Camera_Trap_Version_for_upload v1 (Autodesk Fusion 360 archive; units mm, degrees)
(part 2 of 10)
sketch "Sketch1" plane through (56.25, 0, 0) normal (1, 0, 0) x axis (0, 1, 0)
  line L1 (60.1013, 133) -> (0.1013, 133)
  line L2 (-49.8987, 133) -> (0.1013, 133)
  line L3 (-0.2, 163) -> (14.1326, 163)
  line L4 (16.8, 163) -> (16.8, 163.0335)
  line L5 (-3.2, 103) -> (16.8, 163)
  line L6 (16.8, 103) -> (-3.2, 163)
  line L7 (60, 152.0335) -> (27.8, 152.0335)
  line L8 (60.1013, 133) -> (60, 152.0335)
  line L9 (60.1013, 133) -> (16.8, 133)
  line L10 (60, 100) -> (60, 165)
  line L11 (-3.2, 133) -> (-3.2, 160)
  line L12 (-3.2, 117.4356) -> (-3.2, 119.4382)
  line L13 (-3.2, 133) -> (60.1013, 133)
  line L14 (60.1013, 133) -> (60, 113.9665)
  line L15 (60, 113.9665) -> (27.8, 113.9665)
  line L16 (-0.2, 103) -> (14.1326, 103)
  line L17 (-3.2, 133) -> (-3.2, 106)
  line L18 (6.9663, 163) -> (6.8, 133)
  line L19 (6.9663, 103) -> (6.8, 133)
  line L20 (20, 157) -> (-5, 157)
  line L21 (20, 155.6) -> (20, 157)
  line L22 (-5, 155.6) -> (20, 155.6)
  line L23 (-5, 157) -> (-5, 155.6)
  line L24 (20, 109) -> (-5, 109)
  line L25 (-5, 109) -> (-5, 110.4)
  line L26 (-5, 110.4) -> (20, 110.4)
  line L27 (20, 110.4) -> (20, 109)
  circle C1 centre (6.8, 133) radius 18.4
  circle C2 centre (6.8, 133) radius 16.85
  circle C3 centre (6.8, 133) radius 18.5
  arc A1 centre (27.8, 163.0335) radius 11 clockwise from (27.8, 152.0335) to (17.0613, 160.65)
  arc A2 centre (14.1326, 160) radius 3 clockwise from (14.1326, 163) to (17.0613, 160.65)
  arc A3 centre (-0.2, 160) radius 3 clockwise from (-3.2, 160) to (-0.2, 163)
  arc A4 centre (27.8, 102.9665) radius 11 clockwise from (17.0613, 105.35) to (27.8, 113.9665)
  arc A5 centre (14.1326, 106) radius 3 clockwise from (17.0613, 105.35) to (14.1326, 103)
  arc A6 centre (-0.2, 106) radius 3 clockwise from (-0.2, 103) to (-3.2, 106)
  point P4 (6.8, 133)
  point P12 (6.8, 133)
  point P2 (6.8, 133)
  point P14 (16.8, 133)
  point P11 (16.8, 103)
  point P9 (-3.2, 163)
  point P26 (-3.2, 133)
  point P27 (-3.2, 119.4382)
  point P28 (-3.2, 117.4356)
  point P6 (60.1013, 133)
  point P30 (60.1013, 133)
  point P13 (60, 152.0335)
  point P29 (60, 113.9665)
  point P16 (27.8, 152.0335)
  point P31 (27.8, 113.9665)
  point P18 (14.1326, 163)
  point P35 (14.1326, 103)
  point P19 (17.0613, 160.65)
  point P33 (17.0613, 105.35)
  point P21 (-3.2, 160)
  point P38 (-3.2, 106)
  point P22 (-0.2, 163)
  point P36 (-0.2, 103)
  point P39 (-3.2, 133)
  point P40 (6.8, 133)
  point P41 (6.9663, 163)
  point P42 (6.8, 133)
  point P43 (6.9663, 103)
  point P44 (-5, 157)
  point P48 (-5, 109)
  point P45 (20, 157)
  point P49 (20, 109)
  point P46 (20, 155.6)
  point P51 (20, 110.4)
  point P47 (-5, 155.6)
  point P50 (-5, 110.4)
  point P5 (0.1013, 133)
  point P7 (-49.8987, 133)
  point P10 (-3.2, 103)
  concentric C1 C2
  concentric C1 C3
  horizontal L1
  parallel L1 L2
  coincident P4 L1
  horizontal L3
  perpendicular L3 L11
  parallel L4 L11
  coincident L5 P12
  coincident L6 P12
  coincident P2 P12
  perpendicular L4 L7
  coincident L4 P14
  coincident P11 L4
  tangent L4 A1
  tangent L7 A1
  tangent L3 A2
  tangent A1 A2
  coincident P9 L11
  coincident P9 L3
  tangent A3 L11
  tangent L3 A3
  equal A2 A3
  vertical L10
  coincident L2 P26
  coincident C2 P27
  collinear L11 L12
  coincident C3 P28
  symmetric P6 L2 P30
  symmetric L2 P13 P29
  symmetric L2 P16 P31
  symmetric L2 A1 A4
  symmetric L2 P18 P35
  symmetric L2 P19 P33
  symmetric L2 A2 A5
  symmetric L2 P21 P38
  symmetric L2 P22 P36
  symmetric L2 A3 A6
  symmetric L2 P26 P39
  coincident P4 P40
  midpoint L3 P41
  coincident P4 P42
  midpoint L16 P43
  horizontal L20
  vertical L21
  horizontal L22
  vertical L23
  symmetric L2 P44 P48
  symmetric L2 P45 P49
  symmetric L2 P46 P51
  symmetric L2 P47 P50
  dimension "d254" diameter C2 = 33.7
  dimension "d255" diameter C3 = 37
  dimension "d256" distance P5 P6 = 60
  dimension "d257" distance P5 P7 = 50
  dimension "d258" distance P10 P11 = 20
  dimension "d259" distance P9 P10 = 60
  dimension "d260" radius A1 = 11
  dimension "d261" radius A2 = 3
  dimension "d266" distance P44 P45 = 25
  dimension "d267" distance P44 P47 = 1.4
extrude "Extrude1" new body sketch "Sketch1" profile of C1 C2 C3 L3 L7 L9 A1 A2 L10 L13 L15 A4 A5 L16 L18 L19 L20 L22 L24 L26 distance 5 bodies "interior_motor_holder"
extrude "Extrude2" new body sketch "Sketch1" profile of C1 C2 C3 L3 L12 A3 L16 A6 L17 L18 L19 L20 L22 L24 L26 distance 5 bodies "exterior_motor_holder"
revolve "Revolve1" sketch "Sketch1" AlongAngle 360 bodies "upper_pin"
revolve "Revolve2" sketch "Sketch1" AlongAngle 360 bodies "lower_pin"
combine "Combine1"
combine "Combine2"
combine "Combine3"
combine "Combine4"
sketch "LL_pin" plane through (0, 0, 0) normal (0, 1, 0) x axis (1, 0, 0)
  line L1 (200, 0) -> (-200, 0)
  line L2 (0, -70) -> (0, 0)
  line L3 (-11, -70) -> (5, -70)
  line L4 (-11, -74.1) -> (-11, -70)
  line L5 (5, -70) -> (5, -74.1)
  line L6 (-5, -70) -> (-3, -70)
  line L7 (-5, -75) -> (-5, -74.1)
  line L8 (-3, -75) -> (-5, -75)
  line L9 (-3, -74.1) -> (-3, -75)
  line L10 (-5, -74.1) -> (-11, -74.1)
  line L11 (5, -74.1) -> (-3, -74.1)
  point P1 (0, 0)
  point P4 (0, 0)
  point P10 (-3, -70)
  point P2 (-200, 0)
  point P3 (200, 0)
  point P5 (0, -70)
  point P6 (5, -70)
  point P7 (-11, -70)
  point P9 (5, -74.1)
  point P11 (-5, -70)
  point P13 (-3, -75)
  horizontal L1
  coincident P1 P4
  perpendicular L1 L2
  horizontal L3
  vertical L4
  horizontal L10
  vertical L5
  horizontal L6
  vertical L7
  horizontal L8
  vertical L9
  midpoint L3 P10
  collinear L10 L11
  dimension "d120_3_1" distance P2 P3 = 400
  dimension "d122_3_1" distance P4 P5 = 70
  dimension "d123_3_1" distance P6 P7 = 16 (= "LL_Pin_Length")
  dimension "d124_3_1" distance P6 P9 = 4.1 (= "LL_Pin_half_height")
  dimension "d129_3_1" distance P10 P11 = 2 (= "LL_lip_length")
  dimension "d130_3_1" distance P10 P13 = 5 (= "LL_lip_half_height")
revolve "Revolve1" sketch "LL_pin" AlongAngle 360 named "d131_3_1" bodies "S2_L_Pin"
sketch "LL_pin_falt_face" plane through (5, 0, 0) normal (1, 0, 0) x axis (0, 1, 0)
  line L1 (0, 67) -> (0, 70)
  line L2 (2.8039, 67.0087) -> (-2.8039, 67.0087)
  circle C1 centre (0, 70) radius 4.1
  point P2 (0, 70)
  point P3 (0, 70)
  point P5 (-2.8039, 67.0087)
  point P6 (2.8039, 67.0087)
  coincident P2 P3
  vertical L1
  coincident C1 P5
  coincident C1 P6
  perpendicular L1 L2
extrude "Extrude1" cut sketch "LL_pin_falt_face" profile of C1 L2 against normal blind 5 named "d132_3_1"
fillet "Fillet1" radius 1 named "d135_3_1"
position "Position5"
sketch "Sketch1" plane through (-11, 0, 0) normal (-1, 0, 0) x axis (0, -1, 0)
  circle C1 centre (0, 70) radius 4.1
  circle C2 centre (0, 70) radius 11
  concentric C1 C2
  dimension "d180_1" diameter C2 = 22
extrude "Extrude1" new body sketch "Sketch1" along normal blind 1 named "d181_1" and against normal blind 6 named "d183_1" bodies "L_ball_bearing"
position "Position6"
remove_instance "RemoveInstance12"
position "Position4"
extrude "Extrude14" new body sketch "Tests" profile of C7 C8 along normal blind 3 bodies "348"
extrude "Extrude15" new body sketch "Tests" profile of C9 C10 along normal blind 3 bodies "340"
extrude "Extrude16" new body sketch "Tests" profile of C11 C12 along normal blind 3 bodies "342"
extrude "Extrude17" new body sketch "Tests" profile of C13 C14 along normal blind 3 bodies "344"
extrude "Extrude18" new body sketch "Tests" profile of C13 C14 along normal blind 24 bodies "343"
extrude "Extrude6" cut sketch "Sketch1" profile of C1 C3 L7 along normal blind 1.2
copy_paste "CopyPaste1"
revolve "Revolve1" sketch "Sketch2" AlongAngle 360
revolve "Revolve3" sketch "Sketch2" AlongAngle 360
combine "Combine1" bodies "Mid_gear"
remove_instance "RemoveInstance13"
sketch "Sketch1" plane through (-11, 0, 0) normal (-1, 0, 0) x axis (0, -1, 0)
  circle C1 centre (0, 70) radius 4.1
  circle C2 centre (0, 70) radius 11
  concentric C1 C2
  dimension "d180_2" diameter C2 = 22
extrude "Extrude1" new body sketch "Sketch1" along normal blind 1 named "d181_2" and against normal blind 6 named "d183_2" bodies "L_ball_bearing"
sketch "Sketch1" plane through (0, 0, 0) normal (0, 0, 1) x axis (1, 0, 0)
  curve K1 (31.9963, -0.4887) -> (29.9991, -0.9267)
  curve K2 (31.9963, 0.4887) -> (29.9991, 0.9267)
  curve K3 (29.9991, -0.9267) -> (29.9983, -0.9266)
  curve K4 (29.9991, 0.9267) -> (29.9983, 0.9266)
  line L1 (29.9983, -0.9266) -> (0, 0)
  line L2 (29.9983, 0.9266) -> (0, 0)
  line L3 (0, 0) -> (0, 0)
  line L4 (0, 0) -> (0, 0)
  arc A1 centre (0, 0) radius 32 clockwise from (31.9963, 0.4887) to (31.9963, -0.4887)
sketch "Sketch2" plane through (0, 0, 0) normal (0, 0, 1) x axis (1, 0, 0)
  circle C1 centre (0, 0) radius 29.75
extrude "Extrude1" new body sketch "Sketch2" along normal blind 3 named "d88_1"
sweep "Sweep1" sketch "Sketch1" TwistAngle 1.5 named "d94_1" TaperAngle 0 named "d95_1"
circular_pattern "C-Pattern1" countU 62 named "d96_1" TotalAngle 360 named "d97_1"
combine "Combine1"
work_plane "WorkPlane1" AlongDistance 3 named "d98_1"
mirror "Mirror1" mirrorStitchTolerance 0.01 named "d100_1"
combine "Combine2"
sketch "Sketch3" plane through (0, 0, 0) normal (0, 0, 1) x axis (1, 0, 0)
  curve K1 (87.334, 0) -> (0, 0)
  curve K2 (87.334, 3) -> (87.334, 0)
  curve K3 (0, 3) -> (87.334, 3)
  curve K4 (0, 0) -> (0, 3)
  perpendicular K1 K2
  parallel K1 K3
  parallel K2 K4
position "Position7"
copy_paste "CutPaste4"
combine "Combine5"
combine "Combine1" bodies "Mid_gear"
fillet "Fillet1" radius 3.5
sketch "LL_pin" plane through (0, 0, 0) normal (0, 1, 0) x axis (1, 0, 0)
  line L1 (200, 0) -> (-200, 0)
  line L2 (0, -70) -> (0, 0)
  line L3 (-11, -70) -> (5, -70)
  line L4 (-11, -74.1) -> (-11, -70)
  line L5 (5, -70) -> (5, -74.1)
  line L6 (-5, -70) -> (-3, -70)
  line L7 (-5, -75) -> (-5, -74.1)
  line L8 (-3, -75) -> (-5, -75)
  line L9 (-3, -74.1) -> (-3, -75)
  line L10 (-5, -74.1) -> (-11, -74.1)
  line L11 (5, -74.1) -> (-3, -74.1)
  point P1 (0, 0)
  point P4 (0, 0)
  point P10 (-3, -70)
  point P2 (-200, 0)
  point P3 (200, 0)
  point P5 (0, -70)
  point P6 (5, -70)
  point P7 (-11, -70)
  point P9 (5, -74.1)
  point P11 (-5, -70)
  point P13 (-3, -75)
  horizontal L1
  coincident P1 P4
  perpendicular L1 L2
  horizontal L3
  vertical L4
  horizontal L10
  vertical L5
  horizontal L6
  vertical L7
  horizontal L8
  vertical L9
  midpoint L3 P10
  collinear L10 L11
  dimension "d120_3" distance P2 P3 = 400
  dimension "d122_3" distance P4 P5 = 70
  dimension "d123_3" distance P6 P7 = 16 (= "LL_Pin_Length")
  dimension "d124_3" distance P6 P9 = 4.1 (= "LL_Pin_half_height")
  dimension "d129_3" distance P10 P11 = 2 (= "LL_lip_length")
  dimension "d130_3" distance P10 P13 = 5 (= "LL_lip_half_height")
revolve "Revolve1" sketch "LL_pin" AlongAngle 360 named "d131_3" bodies "S3_L_Pin"
sketch "LL_pin_falt_face" plane through (5, 0, 0) normal (1, 0, 0) x axis (0, 1, 0)
  line L1 (0, 67) -> (0, 70)
  line L2 (2.8039, 67.0087) -> (-2.8039, 67.0087)
  circle C1 centre (0, 70) radius 4.1
  point P2 (0, 70)
  point P3 (0, 70)
  point P5 (-2.8039, 67.0087)
  point P6 (2.8039, 67.0087)
  coincident P2 P3
  vertical L1
  coincident C1 P5
  coincident C1 P6
  perpendicular L1 L2
extrude "Extrude1" cut sketch "LL_pin_falt_face" profile of C1 L2 against normal blind 8 named "d132_3"
position "Position8"
combine "Combine3"
work_plane "WorkPlane1" RotateAngle 0
sketch "Sketch1" plane through (3, 0, 0) normal (-1, 0, 0) x axis (0, 0, 1)
sketch "Sketch1" plane through (0, 0, 0) normal (0, 1, 0) x axis (1, 0, 0)
  line L1 (-5, -185) -> (-5, -207)
  line L2 (-12, -207) -> (-12, -185)
  line L3 (-12, -185) -> (-5, -185)
  line L4 (-12, -207) -> (-5, -207)
  line L5 (5, -193.0087) -> (-3, -193.0087)
  line L6 (5, -200.1) -> (5, -193.0087)
  line L7 (-5, -191.9) -> (-5, -191)
  line L8 (-5, -201) -> (-5, -200.1)
  line L9 (-11, -200.1) -> (-11, -191.9)
  line L10 (-3, -200.1) -> (5, -200.1)
  line L11 (-5, -191) -> (-3, -191)
  line L12 (-5, -201) -> (-3, -201)
  line L13 (-11, -191.9) -> (-5, -191.9)
  line L14 (-11, -200.1) -> (-5, -200.1)
  line L15 (-12.9524, -212.0635) -> (-8, -212.0635)
  line L16 (-15.9524, -182.8039) -> (-15.9524, -209.0635)
  line L17 (-5, -209.0635) -> (-5, -182.8039)
  line L18 (-12, -189.5) -> (-11, -189.5)
  line L19 (-12, -202.5) -> (-12, -189.5)
  line L20 (-11, -202.5) -> (-12, -202.5)
  line L21 (-11, -189.5) -> (-11, -202.5)
  line L22 (-12, -202.5) -> (-11, -189.5)
  line L23 (-11, -202.5) -> (-12, -189.5)
  line L24 (-21, -200.1) -> (-11, -200.1)
  line L25 (-21, -191.9) -> (-21, -200.1)
  line L26 (-11, -191.9) -> (-21, -191.9)
  line L27 (-11, -200.1) -> (-11, -191.9)
  line L28 (-14.134, -166.1795) -> (-5.4019, -181.3039)
  line L29 (15, -182) -> (-5, -182)
  line L30 (5, -182) -> (-15.9524, -182)
  line L31 (-21.7259, -175) -> (-24.9206, -175)
  line L32 (-24.9206, -164.6795) -> (-16.7321, -164.6795)
  line L33 (-25.9206, -175) -> (-25.9206, -164.6795)
  line L34 (-19.1278, -176.5) -> (-16.3543, -181.3039)
  line L35 (-25.9524, -164.6795) -> (-25.9206, -164.7346)
  line L36 (-25.9206, -189) -> (-25.9206, -176)
  line L37 (-25.9206, -159.1567) -> (-25.9206, -163.6795)
  line L38 (-25.9206, -189) -> (-25.9206, -159.1567)
  line L39 (-5, -185) -> (-5, -207)
  line L40 (-5, -207) -> (-12, -207)
  line L41 (-5, -185) -> (-5, -207)
  line L42 (-12, -185) -> (-5, -185)
  line L43 (-12, -207) -> (-12, -185)
  line L44 (-17.5, -200.1) -> (-16.5, -200.1)
  line L45 (-17.5, -191.9) -> (-17.5, -200.1)
  line L46 (-16.5, -191.9) -> (-17.5, -191.9)
  line L47 (-16.5, -200.1) -> (-16.5, -191.9)
  line L48 (-3, -193.0087) -> (-3, -191)
  line L49 (-3, -201) -> (-3, -200.1)
  arc A1 centre (-16.7321, -167.6795) radius 3 clockwise from (-16.7321, -164.6795) to (-14.134, -166.1795)
  arc A2 centre (-21.7259, -178) radius 3 clockwise from (-21.7259, -175) to (-19.1278, -176.5)
  arc A3 centre (-8, -182.8039) radius 3 clockwise from (-5.4019, -181.3039) to (-5, -182.8039)
  arc A4 centre (-8, -209.0635) radius 3 clockwise from (-5, -209.0635) to (-8, -212.0635)
  arc A5 centre (-12.9524, -209.0635) radius 3 clockwise from (-12.9524, -212.0635) to (-15.9524, -209.0635)
  arc A6 centre (-18.9524, -182.8039) radius 3 clockwise from (-16.3543, -181.3039) to (-15.9524, -182.8039)
  arc A7 centre (-24.9206, -176) radius 1 clockwise from (-25.9206, -176) to (-24.9206, -175)
  arc A8 centre (-24.9206, -163.6795) radius 1 clockwise from (-24.9206, -164.6795) to (-25.9206, -163.6795)
  point P26 (-11.5, -196)
  point P15 (-11, -200.1)
  point P27 (-11, -200.1)
  point P36 (-25.9206, -164.7346)
  point P21 (-5, -182)
  point P20 (-15.9524, -182)
  point P34 (-25.9206, -175)
  point P35 (-25.9206, -164.6795)
  point P2 (-5, -207)
  point P63 (-5, -207)
  point P3 (-5, -185)
  point P64 (-5, -185)
  point P5 (-12, -207)
  point P65 (-12, -207)
  point P68 (-16.5, -200.1)
  point P23 (-12, -189.5)
  point P24 (-12, -202.5)
  point P28 (-21, -200.1)
  point P32 (-25.9524, -164.6795)
  point P71 (-16.5, -191.9)
  horizontal L15
  vertical L16
  vertical L17
  horizontal L18
  perpendicular L18 L19
  parallel L18 L20
  parallel L19 L21
  coincident L22 P26
  coincident L23 P26
  horizontal L24
  vertical L25
  horizontal L26
  vertical L27
  coincident P15 P27
  horizontal L29
  horizontal L30
  horizontal L31
  horizontal L32
  vertical L33
  coincident L33 P36
  collinear L34 L35
  tangent L32 A1
  tangent L28 A1
  tangent L31 A2
  tangent L34 A2
  equal A1 A2
  coincident P21 L28
  coincident P21 L17
  tangent L28 A3
  tangent L17 A3
  equal A1 A3
  tangent L17 A4
  tangent L15 A4
  equal A1 A4
  tangent L15 A5
  tangent L16 A5
  equal A1 A5
  coincident P20 L34
  coincident P20 L16
  tangent L34 A6
  tangent L16 A6
  equal A1 A6
  perpendicular L31 L36
  coincident P34 L36
  coincident P34 L31
  tangent L36 A7
  tangent L31 A7
  vertical L37
  coincident P35 L32
  coincident P36 L37
  tangent L32 A8
  tangent L37 A8
  parallel L36 L38
  coincident P2 P63
  coincident P3 P64
  horizontal L40
  vertical L41
  horizontal L42
  vertical L43
  coincident P5 P65
  horizontal L44
  vertical L45
  horizontal L46
  vertical L47
  coincident L24 P68
  dimension "d276" distance P23 P24 = 13
  dimension "d277" distance P27 P28 = 10
  dimension "d278" angle L28 L29 = 120
  dimension "d280" angle L30 L34 = 120
  dimension "d281" distance P20 P32 = 20
  dimension "d282" radius A1 = 3
  dimension "d283" radius A7 = 1
  dimension "d284" radius A8 = 1
  dimension "d293" distance P68 P71 = 8.2
extrude "Extrude1" new body sketch "Sketch1" profile of L1 L2 L3 L4 L7 L8 L9 L13 L14 L15 L16 L17 L18 L19 L20 L21 L24 L26 L27 L28 L35 L31 L32 L33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 distance 13 bodies "Hanger"
fillet "Fillet1" radius 1.5
fillet "Fillet2" radius 1.5
extrude "Extrude2" add of existing geometry blind 10
revolve "Revolve2" sketch "Sketch1" AlongAngle 360
copy_paste "CutPaste1"
combine "Combine1"
combine "Combine2"
sketch "Sketch3" plane through (-12, 0, 0) normal (1, 0, 0) x axis (0, 1, 0)
  circle C1 centre (0, 196) radius 4.1
  circle C2 centre (0, 196) radius 11
  circle C3 centre (0, 196) radius 6.5
  concentric C1 C3
  dimension "d296" diameter C3 = 13
extrude "Extrude2" cut sketch "Sketch3" profile of C1 C3 against normal blind 4
extrude "Extrude19" new body sketch "Tests" profile of C15 C16 C17 C18 C19 C20 C21 C22 L10 L11 L12 L13 along normal blind 3.5 bodies "Distance_Test"
move "Move1"
offset_faces "OffsetFaces1" distance 0.05
offset_faces "OffsetFaces1" distance 0.05
offset_faces "OffsetFaces2" distance 0.05
offset_faces "OffsetFaces1" distance 0.05
combine "Combine1"
sketch "Sketch2" plane through (0, 60, 0) normal (0, 1, 0) x axis (-1, 0, 0)
  line L1 (-61.25, 152.0335) -> (-51.25, 152.0335)
  line L2 (-61.25, 113.9665) -> (-61.25, 152.0335)
  line L3 (-51.25, 113.9665) -> (-61.25, 113.9665)
  line L4 (-51.25, 152.0335) -> (-51.25, 113.9665)
  line L5 (11.8892, 165) -> (-70, 165)
  line L6 (11.8892, 101.3826) -> (11.8892, 165)
  line L7 (-70, 101.3826) -> (11.8892, 101.3826)
  line L8 (-70, 165) -> (-70, 101.3826)
  horizontal L5
  vertical L6
  horizontal L7
  vertical L8
work_plane "WorkPlane1" AlongDistance 0
revolve "Revolve1" sketch "Tests" AlongAngle 360 bodies "Roll_holder"
sketch "Sketch1" plane through (21, 0, 0) normal (1, 0, 0) x axis (0, 1, 0)
  line L1 (1, 62.8936) -> (-1, 62.8936)
  line L2 (1, 77.433) -> (1, 62.8936)
  line L3 (-1, 62.8936) -> (-1, 77.433)
  arc A1 centre (0, 70) radius 7.5 clockwise from (-1, 77.433) to (1, 77.433)
revolve "Revolve2" sketch "Tests" AlongAngle 360 bodies "Roll_holder_34"
revolve "Revolve3" sketch "Tests" AlongAngle 360 bodies "Roll_holder_32"
sketch "Roll_holders" plane through (0, 0, 0) normal (0, 1, 0) x axis (1, 0, 0)
  curve K1 (-18.5, -200.1) -> (-16.5, -200.1)
  curve K2 (-16.5, -191.9) -> (-18.5, -191.9)
  line L1 (-21, -200.1) -> (-21, -191.9)
  line L2 (5, -193.0087) -> (-3, -193.0087)
  line L3 (5, -200.1) -> (5, -193.0087)
  line L4 (-5, -191.9) -> (-5, -191)
  line L5 (-5, -201) -> (-5, -200.1)
  line L6 (-5, -191) -> (-3, -191)
  line L7 (-5, -201) -> (-3, -201)
  line L8 (-16.5, -191.9) -> (-5, -191.9)
  line L9 (-21, -191.9) -> (-18.5, -191.9)
  line L10 (-16.5, -200.1) -> (-5, -200.1)
  line L11 (-21, -200.1) -> (-18.5, -200.1)
  line L12 (0, -227.8815) -> (0, -227.7827)
  line L13 (0, -227.7827) -> (0, -227.4397)
  line L14 (0, -227.4397) -> (0, -227.2429)
  line L15 (0, -227.2429) -> (0, -226.6752)
  line L16 (0, -227.9963) -> (0, -227.8815)
  line L17 (0, -228) -> (0, -227.9963)
  line L18 (0, -164.0037) -> (0, -164)
  line L19 (0, -164.0037) -> (0, -164.1185)
  line L20 (0, -164.2173) -> (0, -164.1185)
  line L21 (0, -164.2173) -> (0, -164.5603)
  line L22 (0, -164.7571) -> (0, -164.5603)
  line L23 (0, -164.7571) -> (0, -165.3248)
  line L24 (0, -165.6174) -> (0, -165.3248)
  line L25 (0, -165.6174) -> (0, -166.4041)
  line L26 (0, -166.7895) -> (0, -166.4041)
  line L27 (0, -166.7895) -> (0, -167.787)
  line L28 (0, -168.2613) -> (0, -167.787)
  line L29 (0, -168.2613) -> (0, -169.4595)
  line L30 (0, -170.0178) -> (0, -169.4595)
  line L31 (0, -170.0178) -> (0, -171.4042)
  line L32 (0, -172.0409) -> (0, -171.4042)
  line L33 (0, -172.0409) -> (0, -173.6014)
  line L34 (0, -174.3098) -> (0, -173.6014)
  line L35 (0, -174.3098) -> (0, -176.0032)
  line L36 (0, -176.0032) -> (0, -176.0038)
  line L37 (0, -176.0038) -> (0, -176.0284)
  line L38 (0, -176.8013) -> (0, -176.0284)
  line L39 (0, -176.8013) -> (0, -178.3701)
  line L40 (0, -178.3701) -> (0, -178.3707)
  line L41 (0, -178.3707) -> (0, -178.5249)
  line L42 (0, -178.6604) -> (0, -178.5249)
  line L43 (0, -179.4899) -> (0, -178.6604)
  line L44 (0, -179.4899) -> (0, -180.918)
  line L45 (0, -180.918) -> (0, -180.9184)
  line L46 (0, -180.9184) -> (0, -181.0503)
  line L47 (0, -181.4703) -> (0, -181.0503)
  line L48 (0, -182.3478) -> (0, -181.4703)
  line L49 (0, -182.3478) -> (0, -183.6205)
  line L50 (0, -183.6205) -> (0, -183.6209)
  line L51 (0, -183.6209) -> (0, -183.7292)
  line L52 (0, -184.4292) -> (0, -183.7292)
  line L53 (0, -185.3458) -> (0, -184.4292)
  line L54 (0, -185.3458) -> (0, -186.4501)
  line L55 (0, -186.4501) -> (0, -186.4504)
  line L56 (0, -186.4504) -> (0, -186.534)
  line L57 (0, -187.4694) -> (0, -186.534)
  line L58 (0, -187.507) -> (0, -187.4694)
  line L59 (0, -188.4532) -> (0, -187.507)
  line L60 (0, -188.4532) -> (0, -189.3777)
  line L61 (0, -189.3777) -> (0, -189.3779)
  line L62 (0, -189.3779) -> (0, -189.4359)
  line L63 (0, -190.5109) -> (0, -189.4359)
  line L64 (0, -190.6718) -> (0, -190.5109)
  line L65 (0, -191.6379) -> (0, -190.6718)
  line L66 (0, -191.6379) -> (0, -192.3733)
  line L67 (0, -192.3733) -> (0, -192.3734)
  line L68 (0, -192.3734) -> (0, -192.4051)
  line L69 (0, -193.5524) -> (0, -192.4051)
  line L70 (0, -193.8913) -> (0, -193.5524)
  line L71 (0, -194.8675) -> (0, -193.8913)
  line L72 (0, -194.8675) -> (0, -195.4061)
  line L73 (0, -195.4061) -> (0, -195.4061)
  line L74 (0, -195.4061) -> (0, -195.4113)
  line L75 (0, -196.5887) -> (0, -195.4113)
  line L76 (0, -196.5939) -> (0, -196.5887)
  line L77 (0, -196.5939) -> (0, -196.5939)
  line L78 (0, -197.1325) -> (0, -196.5939)
  line L79 (0, -198.1087) -> (0, -197.1325)
  line L80 (0, -198.1087) -> (0, -198.4476)
  line L81 (0, -199.5949) -> (0, -198.4476)
  line L82 (0, -199.6266) -> (0, -199.5949)
  line L83 (0, -199.6267) -> (0, -199.6266)
  line L84 (0, -200.3621) -> (0, -199.6267)
  line L85 (0, -201.3282) -> (0, -200.3621)
  line L86 (0, -201.3282) -> (0, -201.4891)
  line L87 (0, -202.5641) -> (0, -201.4891)
  line L88 (0, -202.6221) -> (0, -202.5641)
  line L89 (0, -202.6223) -> (0, -202.6221)
  line L90 (0, -203.5468) -> (0, -202.6223)
  line L91 (0, -204.493) -> (0, -203.5468)
  line L92 (0, -204.493) -> (0, -204.5306)
  line L93 (0, -205.466) -> (0, -204.5306)
  line L94 (0, -205.5496) -> (0, -205.466)
  line L95 (0, -205.5499) -> (0, -205.5496)
  line L96 (0, -206.6542) -> (0, -205.5499)
  line L97 (0, -207.5708) -> (0, -206.6542)
  line L98 (0, -208.2708) -> (0, -207.5708)
  line L99 (0, -208.3791) -> (0, -208.2708)
  line L100 (0, -208.3795) -> (0, -208.3791)
  line L101 (0, -209.6522) -> (0, -208.3795)
  line L102 (0, -210.5297) -> (0, -209.6522)
  line L103 (0, -210.9497) -> (0, -210.5297)
  line L104 (0, -211.0816) -> (0, -210.9497)
  line L105 (0, -211.082) -> (0, -211.0816)
  line L106 (0, -212.5101) -> (0, -211.082)
  line L107 (0, -213.3396) -> (0, -212.5101)
  line L108 (0, -213.4751) -> (0, -213.3396)
  line L109 (0, -213.6293) -> (0, -213.4751)
  line L110 (0, -213.6299) -> (0, -213.6293)
  line L111 (0, -215.1987) -> (0, -213.6299)
  line L112 (0, -215.9716) -> (0, -215.1987)
  line L113 (0, -215.9962) -> (0, -215.9716)
  line L114 (0, -215.9968) -> (0, -215.9962)
  line L115 (0, -217.6902) -> (0, -215.9968)
  line L116 (0, -218.3986) -> (0, -217.6902)
  line L117 (0, -219.9591) -> (0, -218.3986)
  line L118 (0, -220.5958) -> (0, -219.9591)
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  point P279 (6, -196)
  point P283 (21, -196)
  point P285 (6, -216)
  point P280 (21, -196)
  point P286 (26, -196)
  point P288 (21, -211)
  point P287 (26, -211)
  point P289 (44.1262, -202.5476)
  point P292 (122, -196)
  point P293 (117, -196)
  point P295 (122, -211)
  point P294 (117, -211)
  point P296 (98.8738, -202.5477)
  point P298 (127, -196)
  point P300 (122, -216)
  dimension "d335" distance P279 P283 = 15
  dimension "d336" distance P279 P285 = 20
  dimension "d337" distance P280 P286 = 5
  dimension "d338" distance P280 P288 = 15
  dimension "d339" angle = 25
  dimension "d340" distance P287 P289 = 20
  dimension "d342" distance P283 P292 = 101
  dimension "d343" distance P292 P293 = 5
  dimension "d344" distance P292 P295 = 15
  dimension "d345" angle = 155
  dimension "d346" distance P294 P296 = 20
  dimension "d347" distance P292 P298 = 5
  dimension "d348" distance P292 P300 = 20
revolve "Revolve1" sketch "Roll_holders" AlongAngle 360
combine "Combine1" bodies "Gear_roll_holder"
revolve "Revolve1" sketch "Roll_holders" AlongAngle 360 bodies "Roll_holder_R"
sketch "Sketch2" plane through (0, 0, 0) normal (0, 1, 0) x axis (1, 0, 0)
  line L1 (127, -196) -> (127, -216)
  line L2 (122, -196) -> (127, -196)
  line L3 (122, -200.1) -> (122, -196)
  line L4 (127, -200.1) -> (122, -200.1)
  line L5 (127, -196) -> (127, -200.1)
  line L6 (130, -200.1) -> (127, -200.1)
  line L7 (127, -196) -> (130, -196)
  line L8 (130, -202.1) -> (130, -200.1)
  line L9 (132, -202.1) -> (130, -202.1)
  line L10 (132, -200.1) -> (132, -202.1)
  line L11 (130, -196) -> (132, -196)
  line L12 (138, -200.1) -> (132, -200.1)
  line L13 (138, -196) -> (138, -200.1)
  line L14 (132, -196) -> (138, -196)
  point P2 (127, -216)
  point P3 (127, -196)
  point P4 (122, -196)
  point P6 (127, -200.1)
  point P7 (130, -200.1)
  point P9 (130, -202.1)
  point P10 (132, -202.1)
  point P12 (132, -200.1)
  point P13 (138, -200.1)
  point P14 (138, -196)
  vertical L1
  horizontal L2
  vertical L3
  horizontal L4
  vertical L5
  perpendicular L5 L6
  perpendicular L6 L8
  perpendicular L8 L9
  perpendicular L9 L10
  perpendicular L10 L12
  perpendicular L12 L13
  dimension "d359" distance P2 P3 = 20
  dimension "d370" distance P3 P4 = 5
  dimension "d371" distance P3 P6 = 4.1
  dimension "d372" distance P6 P7 = 3
  dimension "d373" distance P7 P9 = 2
  dimension "d374" distance P9 P10 = 2
  dimension "d375" distance P12 P13 = 6
  dimension "d376" distance P13 P14 = 4.1
revolve "Revolve2" sketch "Sketch2" AlongAngle 360
sketch "Sketch4" plane through (138, 0, 0) normal (1, 0, 0) x axis (0, 1, 0)
  line L1 (0, 193) -> (0, 196)
  line L2 (2.8104, 193.0148) -> (-2.8104, 193.0148)
  circle C1 centre (0, 196) radius 4.1
  point P2 (0, 196)
  point P3 (0, 196)
  point P5 (-2.8104, 193.0148)
  point P6 (2.8104, 193.0148)
  point P4 (0, 193)
  coincident P2 P3
  vertical L1
  coincident C1 P5
  coincident C1 P6
  horizontal L2
  dimension "d378" distance P3 P4 = 3
sketch "Sketch5" plane through (122, 0, 0) normal (-1, 0, 0) x axis (0, -1, 0)
  line L1 (0, 193) -> (0, 196)
  line L2 (2.7892, 192.995) -> (-2.7892, 192.995)
  circle C1 centre (0, 196) radius 4.1
  point P2 (0, 196)
  point P3 (0, 196)
  point P5 (-2.7892, 192.995)
  point P6 (2.7892, 192.995)
  point P4 (0, 193)
  coincident P2 P3
  vertical L1
  coincident C1 P5
  coincident C1 P6
  perpendicular L1 L2
  dimension "d381" distance P3 P4 = 3
extrude "Extrude2" cut sketch "Sketch5" profile of C1 L2 against normal blind 4
combine "Combine1"
sketch "Sketch2" plane through (138, 0, 0) normal (1, 0, 0) x axis (0, 1, 0)
  circle C1 centre (0, 196) radius 4.1
  circle C2 centre (0, 196) radius 11
  concentric C1 C2
  dimension "d384" diameter C2 = 22
extrude "Extrude1" new body sketch "Sketch2" along normal blind 1 and against normal blind 6
copy_paste_bodies "CutPasteBodies1"
sketch "Sketch3" plane through (139, 0, 0) normal (1, 0, 0) x axis (0, 1, 0)
  circle C1 centre (0, 196) radius 4.1
  circle C2 centre (0, 196) radius 11
  circle C3 centre (0, 196) radius 20
  concentric C1 C3
  dimension "d389" diameter C3 = 40
extrude "Extrude2" new body sketch "Sketch3" against normal blind 7
copy_paste_bodies "CutPasteBodies1"
extrude "Extrude3" new body of existing geometry blind 30
copy_paste_bodies "CutPasteBodies2"
combine "Combine1"
extrude "Extrude1" cut of existing geometry blind -7
sketch "Sketch1" plane through (169, 0, 0) normal (1, 0, 0) x axis (0, 1, 0)
  circle C1 centre (0, 196) radius 20
  circle C2 centre (0, 196) radius 6.5
  concentric C1 C2
  dimension "d396" diameter C2 = 13
cylinder_primitive "CylinderPrimitive1" sketch "Sketch2" Height 2 Diameter 13
extrude "Extrude3" cut of existing geometry blind -15
combine "Combine2"
fillet "Fillet1" radius 3
move "Move1"
position "Position9"
extrude "Extrude3" cut of existing geometry blind -3
position "Position10"
extrude "Extrude4" cut of existing geometry blind -10
sketch "Sketch1" plane through (0, 50, 0) normal (0, 1, 0) x axis (-1, 0, 0)
  line L1 (-61.25, 152.0335) -> (-51.25, 152.0335)
  line L2 (-61.25, 113.9665) -> (-61.25, 152.0335)
  line L3 (-51.25, 113.9665) -> (-61.25, 113.9665)
  line L4 (-51.25, 152.0335) -> (-51.25, 113.9665)
  line L5 (-129, 216) -> (-129, 196)
  line L6 (-129, 176) -> (-136, 176)
  line L7 (-129, 216) -> (-136, 216)
  line L8 (-136, 85) -> (-136, 55)
  line L9 (-129, 85) -> (-129, 55)
  line L10 (-136, 45) -> (-136, 55)
  line L11 (-129, 55) -> (-129, 45)
  line L12 (-129, 45) -> (-136, 45)
  line L13 (-129, 95) -> (-136, 95)
  line L14 (-136, 85) -> (-136, 95)
  line L15 (-129, 95) -> (-129, 85)
  line L16 (5, 58.9) -> (5, 81.1)
  line L17 (12, 58.9) -> (12, 81.1)
  line L18 (12, 58.9) -> (5, 58.9)
  line L19 (12, 81.1) -> (5, 81.1)
  line L20 (5, 121.9) -> (5, 144.1)
  line L21 (12, 121.9) -> (12, 144.1)
  line L22 (12, 121.9) -> (5, 121.9)
  line L23 (12, 144.1) -> (5, 144.1)
  line L24 (2, 209.0635) -> (2, 182.8039)
  line L25 (22.9206, 163.6795) -> (22.9206, 176)
  line L26 (21.9206, 175) -> (18.7259, 175)
  line L27 (13.7321, 164.6795) -> (21.9206, 164.6795)
  line L28 (2.4019, 181.3039) -> (11.134, 166.1795)
  line L29 (9.9524, 212.0635) -> (5, 212.0635)
  line L30 (12.9524, 182.8039) -> (12.9524, 209.0635)
  line L31 (16.1278, 176.5) -> (13.3543, 181.3039)
  line L32 (-61.25, 149.8497) -> (-61.25, 163)
  line L33 (-61.25, 116.1503) -> (-61.25, 149.8497)
  line L34 (-61.25, 103) -> (-61.25, 116.1503)
  line L35 (-54.8877, 110.7228) -> (-57.6123, 110.7228)
  line L36 (-57.6123, 155.2772) -> (-54.8877, 155.2772)
  line L37 (-51.25, 116.1503) -> (-51.25, 103)
  line L38 (-51.25, 149.8497) -> (-51.25, 116.1503)
  line L39 (-51.25, 163) -> (-51.25, 149.8497)
  line L40 (-61.25, 163) -> (-51.25, 163)
  line L41 (-61.25, 103) -> (-51.25, 103)
  line L42 (-5, 200.1) -> (-5, 193.0087)
  line L43 (-5, 193.0087) -> (0, 193.0087)
  curve K1 (15.5, 200.1) -> (13.5, 200.1)
  curve K2 (13.5, 191.9) -> (15.5, 191.9)
  line L44 (18, 200.1) -> (18, 191.9)
  line L45 (0, 193.0087) -> (0, 191)
  line L46 (0, 201) -> (0, 200.1)
  line L47 (2, 191.9) -> (2, 191)
  line L48 (2, 201) -> (2, 200.1)
  line L49 (2, 191) -> (0, 191)
  line L50 (2, 201) -> (0, 201)
  line L51 (13.5, 191.9) -> (2, 191.9)
  line L52 (18, 191.9) -> (15.5, 191.9)
  line L53 (13.5, 200.1) -> (2, 200.1)
  line L54 (18, 200.1) -> (15.5, 200.1)
  line L55 (0, 200.1) -> (-5, 200.1)
  line L56 (20, 200.1) -> (18, 200.1)
  line L57 (20, 101) -> (20, 200.1)
  line L58 (-139, 230) -> (-139, 40)
  line L59 (-136, 176) -> (-136, 196)
  line L60 (-129, 196) -> (-129, 176)
  line L61 (-136, 196) -> (-136, 216)
  arc A1 centre (21.9206, 176) radius 1 clockwise from (22.9206, 176) to (21.9206, 175)
  arc A2 centre (21.9206, 163.6795) radius 1 clockwise from (21.9206, 164.6795) to (22.9206, 163.6795)
  arc A3 centre (13.7321, 167.6795) radius 3 clockwise from (13.7321, 164.6795) to (11.134, 166.1795)
  arc A4 centre (5, 182.8039) radius 3 clockwise from (2.4019, 181.3039) to (2, 182.8039)
  arc A5 centre (5, 209.0635) radius 3 clockwise from (2, 209.0635) to (5, 212.0635)
  arc A6 centre (9.9524, 209.0635) radius 3 clockwise from (9.9524, 212.0635) to (12.9524, 209.0635)
  arc A7 centre (15.9524, 182.8039) radius 3 clockwise from (13.3543, 181.3039) to (12.9524, 182.8039)
  arc A8 centre (18.7259, 178) radius 3 clockwise from (18.7259, 175) to (16.1278, 176.5)
  arc A9 centre (-56.25, 110.4) radius 1.4 clockwise from (-54.8877, 110.7228) to (-57.6123, 110.7228)
  arc A10 centre (-56.25, 155.6) radius 1.4 clockwise from (-57.6123, 155.2772) to (-54.8877, 155.2772)
  point P73 (18, 200.1)
  point P81 (18, 200.1)
  coincident P73 P81
  perpendicular L44 L56
  perpendicular L54 L57
  perpendicular L7 L58
sketch "Sketch3" plane through (0, 0, 0) normal (0, 1, 0) x axis (1, 0, 0)
  line L1 (129, -216) -> (129, -196)
  line L2 (129, -196) -> (129, -176)
  line L3 (148, -216) -> (129, -216)
  line L4 (148, -176) -> (129, -176)
  line L5 (123, -192.995) -> (119, -192.995)
  line L6 (123, -191.9) -> (123, -192.995)
  line L7 (119, -200.1) -> (119, -192.995)
  line L8 (135, -200.1) -> (135, -191.9)
  line L9 (129, -191.9) -> (129, -189.9)
  line L10 (129, -202.1) -> (129, -200.1)
  line L11 (127, -191.9) -> (127, -189.9)
  line L12 (127, -202.1) -> (127, -200.1)
  line L13 (129, -191.9) -> (135, -191.9)
  line L14 (129, -200.1) -> (135, -200.1)
  line L15 (127, -189.9) -> (129, -189.9)
  line L16 (127, -202.1) -> (129, -202.1)
  line L17 (123, -191.9) -> (127, -191.9)
  line L18 (119, -200.1) -> (127, -200.1)
  line L19 (127, -216) -> (127, -176)
  line L20 (122, -181) -> (122, -176)
  line L21 (122, -216) -> (122, -211)
  line L22 (98.8738, -202.5477) -> (98.8738, -189.4524)
  line L23 (122, -176) -> (127, -176)
  line L24 (122, -216) -> (127, -216)
  line L25 (117, -181) -> (122, -181)
  line L26 (117, -211) -> (122, -211)
  line L27 (117, -211) -> (98.8738, -202.5477)
  line L28 (117, -181) -> (98.8738, -189.4524)
  line L29 (21, -181) -> (21, -176)
  line L30 (21, -216) -> (21, -211)
  line L31 (44.1262, -202.5476) -> (44.1262, -189.4524)
  line L32 (0, -227.8815) -> (0, -227.7827)
  line L33 (0, -227.7827) -> (0, -227.4397)
  line L34 (0, -227.4397) -> (0, -227.2429)
  line L35 (0, -227.2429) -> (0, -226.6752)
  line L36 (0, -227.9963) -> (0, -227.8815)
  line L37 (0, -228) -> (0, -227.9963)
  line L38 (0, -164.0037) -> (0, -164)
  line L39 (0, -164.0037) -> (0, -164.1185)
  line L40 (0, -164.2173) -> (0, -164.1185)
  line L41 (0, -164.2173) -> (0, -164.5603)
  line L42 (0, -164.7571) -> (0, -164.5603)
  line L43 (0, -164.7571) -> (0, -165.3248)
  line L44 (0, -165.6174) -> (0, -165.3248)
  line L45 (0, -165.6174) -> (0, -166.4041)
  line L46 (0, -166.7895) -> (0, -166.4041)
  line L47 (0, -166.7895) -> (0, -167.787)
  line L48 (0, -168.2613) -> (0, -167.787)
  line L49 (0, -168.2613) -> (0, -169.4595)
  line L50 (0, -170.0178) -> (0, -169.4595)
  line L51 (0, -170.0178) -> (0, -171.4042)
  line L52 (0, -172.0409) -> (0, -171.4042)
  line L53 (0, -172.0409) -> (0, -173.6014)
  line L54 (0, -174.3098) -> (0, -173.6014)
  line L55 (0, -174.3098) -> (0, -176.0032)
  line L56 (0, -176.0032) -> (0, -176.0038)
  line L57 (0, -176.0038) -> (0, -176.0284)
  line L58 (0, -176.8013) -> (0, -176.0284)
  line L59 (0, -176.8013) -> (0, -178.3701)
  line L60 (0, -178.3701) -> (0, -178.3707)
  line L61 (0, -178.3707) -> (0, -178.5249)
  line L62 (0, -178.6604) -> (0, -178.5249)
  line L63 (0, -179.4899) -> (0, -178.6604)
  line L64 (0, -179.4899) -> (0, -180.918)
  line L65 (0, -180.918) -> (0, -180.9184)
  line L66 (0, -180.9184) -> (0, -181.0503)
  line L67 (0, -181.4703) -> (0, -181.0503)
  line L68 (0, -182.3478) -> (0, -181.4703)
  line L69 (0, -182.3478) -> (0, -183.6205)
  line L70 (0, -183.6205) -> (0, -183.6209)
  line L71 (0, -183.6209) -> (0, -183.7292)
  line L72 (0, -184.4292) -> (0, -183.7292)
  line L73 (0, -185.3458) -> (0, -184.4292)
  line L74 (0, -185.3458) -> (0, -186.4501)
  line L75 (0, -186.4501) -> (0, -186.4504)
  line L76 (0, -186.4504) -> (0, -186.534)
  line L77 (0, -187.4694) -> (0, -186.534)
  line L78 (0, -187.507) -> (0, -187.4694)
  line L79 (0, -188.4532) -> (0, -187.507)
  line L80 (0, -188.4532) -> (0, -189.3777)
  line L81 (0, -189.3777) -> (0, -189.3779)
  line L82 (0, -189.3779) -> (0, -189.4359)
  line L83 (0, -190.5109) -> (0, -189.4359)
  line L84 (0, -190.6718) -> (0, -190.5109)
  line L85 (0, -191.6379) -> (0, -190.6718)
  line L86 (0, -191.6379) -> (0, -192.3733)
  line L87 (0, -192.3733) -> (0, -192.3734)
  line L88 (0, -192.3734) -> (0, -192.4051)
  line L89 (0, -193.5524) -> (0, -192.4051)
  line L90 (0, -193.8913) -> (0, -193.5524)
  line L91 (0, -194.8675) -> (0, -193.8913)
  line L92 (0, -194.8675) -> (0, -195.4061)
  line L93 (0, -195.4061) -> (0, -195.4061)
  line L94 (0, -195.4061) -> (0, -195.4113)
  line L95 (0, -196.5887) -> (0, -195.4113)
  line L96 (0, -196.5939) -> (0, -196.5887)
  line L97 (0, -196.5939) -> (0, -196.5939)
  line L98 (0, -197.1325) -> (0, -196.5939)
  line L99 (0, -198.1087) -> (0, -197.1325)
  line L100 (0, -198.1087) -> (0, -198.4476)
  line L101 (0, -199.5949) -> (0, -198.4476)
  line L102 (0, -199.6266) -> (0, -199.5949)
  line L103 (0, -199.6267) -> (0, -199.6266)
  line L104 (0, -200.3621) -> (0, -199.6267)
  line L105 (0, -201.3282) -> (0, -200.3621)
  line L106 (0, -201.3282) -> (0, -201.4891)
  line L107 (0, -202.5641) -> (0, -201.4891)
  line L108 (0, -202.6221) -> (0, -202.5641)
  line L109 (0, -202.6223) -> (0, -202.6221)
  line L110 (0, -203.5468) -> (0, -202.6223)
  line L111 (0, -204.493) -> (0, -203.5468)
  line L112 (0, -204.493) -> (0, -204.5306)
  line L113 (0, -205.466) -> (0, -204.5306)
  line L114 (0, -205.5496) -> (0, -205.466)
  line L115 (0, -205.5499) -> (0, -205.5496)
  line L116 (0, -206.6542) -> (0, -205.5499)
  line L117 (0, -207.5708) -> (0, -206.6542)
  line L118 (0, -208.2708) -> (0, -207.5708)
  line L119 (0, -208.3791) -> (0, -208.2708)
  line L120 (0, -208.3795) -> (0, -208.3791)
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  point P34 (21, -216)
  point P803 (21, -216)
  point P26 (122, -216)
  point P804 (122, -216)
  point P519 (21, -77.5)
  point P805 (21, -77.5)
  point P521 (122, -77.5)
  point P806 (122, -77.5)
  point P514 (-12, -58.9)
  point P807 (-12, -58.9)
  point P790 (139, -40)
  point P824 (139, -40)
  point P826 (122, -77.5)
  point P838 (143.8734, -216)
  point P808 (-19, -58.9)
  point P839 (143.8734, -221)
  coincident P34 P803
  coincident P26 P804
  coincident P519 P805
  coincident P521 P806
  coincident P514 P807
  coincident P790 P824
  coincident P521 P826
  coincident L3 P838
  dimension "d404" distance P807 P808 = 7
  dimension "d431" distance P838 P839 = 5
combine "Combine1" bodies "Handle_assembled"
thread "Thread1" ThreadOffset 0 ThreadLength 10
sketch "Sketch3" plane through (151, 0, 0) normal (1, 0, 0) x axis (0, 1, 0)
  line L1 (-7.5, 201) -> (7.5, 201)
  line L2 (-10, 193.5) -> (-10, 198.5)
  line L3 (7.5, 191) -> (-7.5, 191)
  line L4 (10, 198.5) -> (10, 193.5)
  line L5 (-10, 191) -> (10, 201)
  line L6 (10, 191) -> (-10, 201)
  circle C1 centre (0, 196) radius 16.8822
  arc A1 centre (-7.5, 198.5) radius 2.5 clockwise from (-10, 198.5) to (-7.5, 201)
  arc A2 centre (-7.5, 193.5) radius 2.5 clockwise from (-7.5, 191) to (-10, 193.5)
  arc A3 centre (7.5, 193.5) radius 2.5 clockwise from (10, 193.5) to (7.5, 191)
  arc A4 centre (7.5, 198.5) radius 2.5 clockwise from (7.5, 201) to (10, 198.5)
  point P7 (0, 196)
  point P2 (0, 196)
  point P4 (-10, 201)
  point P5 (-10, 191)
  point P6 (10, 191)
  point P3 (10, 201)
  horizontal L1
  perpendicular L1 L2
  parallel L1 L3
  parallel L2 L4
  coincident L5 P7
  coincident L6 P7
  coincident P2 P7
  coincident P4 L1
  coincident P4 L2
  tangent L1 A1
  tangent L2 A1
  coincident P5 L2
  coincident P5 L3
  tangent L2 A2
  tangent L3 A2
  equal A1 A2
  coincident P6 L3
  coincident P6 L4
  tangent L3 A3
  tangent L4 A3
  equal A1 A3
  coincident P3 L4
  coincident P3 L1
  tangent L4 A4
  tangent L1 A4
  equal A1 A4
  dimension "d417" distance P5 P6 = 20
  dimension "d418" distance P4 P5 = 10
  dimension "d419" radius A1 = 2.5
extrude "Extrude4" new body sketch "Sketch3" profile of L1 L2 L3 L4 A1 A2 A3 A4 along normal blind 5
combine "Combine2"
fillet "Fillet1" radius 1.5
fillet "Fillet2" radius 1
work_plane "WorkPlane1" AlongDistance -10
sketch "Sketch1" plane through (139, 0, 0) normal (-1, 0, 0) x axis (0, -1, 0)
  circle C1 centre (0, 196) radius 25
  dimension "d427" diameter C1 = 50
extrude "Extrude1" new body sketch "Sketch1" against normal blind 7 bodies "nut_test"
combine "Combine3"
offset_faces "OffsetFaces1" distance -0.2
move "Move1"
sketch "Sketch1" plane through (-9, 0, 0) normal (-1, 0, 0) x axis (0, -1, 0)
  line L1 (-45, 211) -> (0, 211)
  line L2 (-50, 181) -> (-50, 211)
  line L3 (0, 181) -> (-45, 181)
  line L4 (0, 211) -> (0, 181)
  line L5 (-50, 216) -> (-50, 225)
  line L6 (-50, 95) -> (-50, 176)
  line L7 (-50, 176) -> (-50, 216)
  circle C1 centre (0, 196) radius 4.1
  circle C2 centre (0, 196) radius 11.05
  circle C3 centre (0, 196) radius 15
  arc A1 centre (-45, 216) radius 5 clockwise from (-45, 211) to (-50, 216)
  arc A2 centre (-45, 176) radius 5 clockwise from (-50, 176) to (-45, 181)
  point P4 (0, 211)
  point P5 (-50, 211)
  point P6 (-50, 181)
  concentric C1 C3
  horizontal L1
  vertical L2
  horizontal L3
  vertical L4
  coincident C3 P4
  perpendicular L1 L5
  coincident P5 L1
  tangent L1 A1
  tangent L5 A1
  perpendicular L3 L6
  coincident P6 L3
  coincident P6 L6
  tangent L3 A2
  tangent L6 A2
  tangent A2 L7
  dimension "d432" diameter C3 = 30
  dimension "d433" radius A1 = 5
  dimension "d434" radius A2 = 5
extrude "Extrude1" new body sketch "Sketch1" profile of C1 C2 C3 L1 L2 L3 L4 A1 A2 L7 along normal blind 3 and against normal blind 7
sketch "Sketch2" plane through (-2, 0, 0) normal (1, 0, 0) x axis (0, 1, 0)
  circle C1 centre (0, 196) radius 4.1
  circle C2 centre (0, 196) radius 11.05
extrude "Extrude2" cut sketch "Sketch2" against normal blind 7
sketch "Sketch3" plane through (-9, 0, 0) normal (1, 0, 0) x axis (0, 1, 0)
  circle C1 centre (0, 196) radius 11.05
  circle C2 centre (0, 196) radius 6.5
  concentric C1 C2
  dimension "d444" diameter C2 = 13
extrude "Extrude3" cut sketch "Sketch3" profile of C2 against normal blind 3
fillet "Fillet1" radius 2
sketch "Sketch4" plane through (-2, 0, 0) normal (1, 0, 0) x axis (0, 1, 0)
  line L1 (45, 181) -> (0, 181)
  line L2 (50, 216) -> (50, 176)
  line L3 (0, 211) -> (45, 211)
  circle C1 centre (0, 196) radius 11.05
  arc A1 centre (45, 176) radius 5 clockwise from (45, 181) to (50, 176)
  arc A2 centre (45, 216) radius 5 clockwise from (50, 216) to (45, 211)
  arc A3 centre (0, 196) radius 15 clockwise from (0, 181) to (0, 211)
fillet "Fillet2" radius 2
copy_paste_bodies "CopyPasteBodies1"
move "Move1"
position "Position11"
copy_paste_bodies "CutPasteBodies1"
extrude "Extrude4" cut of existing geometry blind -3
sketch "Sketch1" plane through (-9, 0, 0) normal (-1, 0, 0) x axis (0, -1, 0)
  circle C1 centre (0, 196.6) radius 4.1
  circle C2 centre (0, 196.6) radius 11
work_plane "WorkPlane1" AlongDistance -7
sketch "Sketch2" plane through (-5, 0, 0) normal (-1, 0, 0) x axis (0, -1, 0)
  line L1 (0, 70.6) -> (0, 0)
  circle C1 centre (0, 70.6) radius 11.1
  circle C2 centre (0, 70.6) radius 13.1
  circle C3 centre (0, 70.6) radius 6.5
  point P1 (0, 0)
  point P2 (0, 0)
  point P3 (0, 70.6)
  point P4 (0, 70.6)
  coincident P1 P2
  vertical L1
  coincident P3 P4
  concentric C1 C2
  concentric C2 C3
  dimension "d469" distance P2 P3 = 70.6
  dimension "d470" diameter C1 = 22.2
  dimension "d471" diameter C2 = 26.2
  dimension "d472" diameter C3 = 13
extrude "Extrude3" new body sketch "Sketch2" profile of C1 C2 along normal blind 7 bodies "Left_Wall_Cap_Low"
extrude "Extrude4" new body sketch "Sketch2" profile of C1 C2 C3 blind 2 from offset 7
extrude "Extrude5" cut sketch "Sketch2" profile of C3 blind 1 from offset 7
combine "Combine1"
copy_paste_bodies "CopyPasteBodies1"
copy_paste_bodies "CopyPasteBodies1"
move "Move1" TranslateX 0 TranslateY 0 TranslateZ 62.6
sketch "Sketch4" plane through (-14, 0, 0) normal (-1, 0, 0) x axis (0, -1, 0)
  line L1 (15, 100.6) -> (-15, 100.6)
  line L2 (-30, 85.6) -> (-30, 55.6)
  line L3 (-15, 40.6) -> (15, 40.6)
  line L4 (30, 55.6) -> (30, 85.6)
  line L5 (-50, 215.4) -> (-50, 210.501)
  line L6 (0, 210.4) -> (-45, 210.4)
  line L7 (-45, 180.4) -> (0, 180.4)
  line L8 (-50, 180.299) -> (-50, 175.4)
  line L9 (-50, 210.501) -> (-50, 180.299)
  line L10 (-50, 152.0335) -> (-50, 113.9665)
  line L11 (-27.8, 152.0335) -> (-50, 152.0335)
  line L12 (-6.9663, 163) -> (-14.1326, 163)
  line L13 (-6.8934, 149.8497) -> (-6.9663, 163)
  line L14 (-6.9663, 103) -> (-6.8934, 116.1503)
  line L15 (-14.1326, 103) -> (-6.9663, 103)
  line L16 (-50, 113.9665) -> (-27.8, 113.9665)
  line L17 (-50, 0) -> (-50, 250)
  line L18 (50, 0) -> (-50, 0)
  line L19 (0, 219.4) -> (0, 215.4)
  line L20 (30, 40.6) -> (-50, 40.6)
  line L21 (50, 40.6) -> (-50, 40.6)
  line L22 (50, 170.6) -> (50, 60.6)
  line L23 (-50, 170.6) -> (50, 170.6)
  line L24 (-50, 40.6) -> (-50, 170.6)
  circle C1 centre (0, 70.6) radius 13.1
  circle C2 centre (-27.5, 70.6) radius 1
  circle C3 centre (27.5, 70.6) radius 1
  circle C4 centre (0, 43.1) radius 1
  circle C5 centre (0, 98.1) radius 1
  arc A1 centre (-15, 85.6) radius 15 clockwise from (-30, 85.6) to (-15, 100.6)
  arc A2 centre (-15, 55.6) radius 15 clockwise from (-15, 40.6) to (-30, 55.6)
  arc A3 centre (15, 55.6) radius 15 clockwise from (30, 55.6) to (15, 40.6)
  arc A4 centre (15, 85.6) radius 15 clockwise from (15, 100.6) to (30, 85.6)
  arc A5 centre (-45, 215.4) radius 5 clockwise from (-45, 210.4) to (-50, 215.4)
  arc A6 centre (0, 195.4) radius 15 clockwise from (0, 210.4) to (0, 180.4)
  arc A7 centre (-45, 175.4) radius 5 clockwise from (-50, 175.4) to (-45, 180.4)
  circle C6 centre (0, 195.4) radius 6.5
  arc A8 centre (-27.8, 163.0335) radius 11 clockwise from (-17.0613, 160.65) to (-27.8, 152.0335)
  arc A9 centre (-14.1326, 160) radius 3 clockwise from (-17.0613, 160.65) to (-14.1326, 163)
  arc A10 centre (-6.8, 133) radius 16.85 clockwise from (-6.8934, 116.1503) to (-6.8934, 149.8497)
  arc A11 centre (-14.1326, 106) radius 3 clockwise from (-14.1326, 103) to (-17.0613, 105.35)
  arc A12 centre (-27.8, 102.9665) radius 11 clockwise from (-27.8, 113.9665) to (-17.0613, 105.35)
  circle C7 centre (0, 195.4) radius 20
  arc A13 centre (30, 60.6) radius 20 clockwise from (50, 60.6) to (30, 40.6)
  circle C8 centre (0, 133.2) radius 13.1
  circle C9 centre (0, 70.6) radius 13.1
  point P51 (0, 215.4)
  point P53 (-50, 40.6)
  point P54 (50, 40.6)
  point P49 (-50, 0)
  point P50 (50, 0)
  point P52 (0, 219.4)
  point P56 (-50, 170.6)
  parallel L10 L17
  perpendicular L17 L18
  coincident C7 P51
  perpendicular L6 L19
  coincident L17 P53
  perpendicular L17 L20
  horizontal L21
  vertical L22
  horizontal L23
  vertical L24
  coincident P54 L22
  tangent L22 A13
  tangent L20 A13
  dimension "d487" distance P49 P50 = 100
  dimension "d488" distance P51 P52 = 4
  dimension "d489" distance P53 P54 = 100
  dimension "d490" distance P53 P56 = 130
  dimension "d491" radius A13 = 20
extrude "Extrude6" new body sketch "Sketch4" profile of C1 C2 C3 C4 C5 L1 A1 L2 A2 L3 A3 L4 A4 L10 L11 A8 A9 L12 L13 A10 L14 L15 A11 A12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 along normal blind 5 and against normal blind 3 bodies "Extrusion_Wall"
extrude "Extrude7" new body sketch "Sketch4" profile of C1 C8 C9 along normal blind 5 bodies "Extrusion_hole Mid", "Extrusion_hold_Upper"
combine "Combine3"
sketch "Sketch5" plane through (0, -50, 0) normal (0, -1, 0) x axis (1, 0, 0)
  line L1 (-19, 170.6) -> (-11, 170.6)
  line L2 (-19, 60.6) -> (-19, 170.6)
  line L3 (-11, 60.6) -> (-19, 60.6)
  line L4 (-11, 170.6) -> (-11, 60.6)
  line L5 (-15, 199.4075) -> (-15, 191.3925)
  curve K1 (-15, 191.3925) -> (-13.5, 191.3)
  curve K2 (-13.5, 199.5) -> (-15, 199.4075)
  line L6 (5, 192.4087) -> (5, 199.5)
  line L7 (0, 192.4087) -> (5, 192.4087)
  line L8 (0, 199.5) -> (0, 200.4)
  line L9 (0, 190.4) -> (0, 192.4087)
  line L10 (-2, 199.5) -> (-2, 200.4)
  line L11 (-2, 190.4) -> (-2, 191.3)
  line L12 (-13.5, 199.5) -> (-2, 199.5)
  line L13 (-13.5, 191.3) -> (-2, 191.3)
  line L14 (-2, 200.4) -> (0, 200.4)
  line L15 (-2, 190.4) -> (0, 190.4)
  line L16 (0, 199.5) -> (5, 199.5)
  line L17 (-18, 199.4075) -> (-15, 199.4075)
  line L18 (-25, 170.6063) -> (-11, 170.6063)
  line L19 (-30, 215) -> (-30, 175.6063)
  line L20 (-32, 163.6063) -> (-11, 163.6063)
  line L21 (-37, 215) -> (-37, 168.6063)
  line L22 (-11, 163.6063) -> (-11, 170.6063)
  line L23 (-30, 215) -> (-37, 215)
  line L24 (-11, 163.6063) -> (-11, 170.6063)
  arc A1 centre (-32, 168.6063) radius 5 clockwise from (-32, 163.6063) to (-37, 168.6063)
  arc A2 centre (-25, 175.6063) radius 5 clockwise from (-25, 170.6063) to (-30, 175.6063)
  point P7 (-15, 199.4075)
  point P20 (-15, 199.4075)
  point P22 (-11, 170.6063)
  point P21 (-18, 199.4075)
  coincident P7 P20
  perpendicular L5 L17
  coincident L4 P22
  perpendicular L4 L18
  perpendicular L18 L19
  tangent L20 A1
  tangent L21 A1
  perpendicular L20 L22
  tangent L19 A2
  tangent L18 A2
  perpendicular L19 L23
  dimension "d502" distance P20 P21 = 3
  dimension "d504" radius A1 = 5
  dimension "d505" radius A2 = 5
extrude "Extrude8" add sketch "Sketch5" profile of L1 L2 L18 L19 L20 L21 A1 A2 L23 L24 against normal blind 100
